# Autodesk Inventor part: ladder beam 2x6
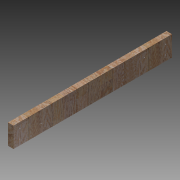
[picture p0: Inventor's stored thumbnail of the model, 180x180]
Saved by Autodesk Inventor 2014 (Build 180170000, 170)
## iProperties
Created: 2013-07
Part Number: ladder beam 2x6
Material: Generic
Document SubType Name: Modeling
Designer: Patrick Rice
Density: 1 g/cm^3
Appearance: Default
Author: Patrick Rice
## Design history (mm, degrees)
sketch "Sketch1"
  geometry: L1 (19.05, -69.85)-(-19.05, -69.85); L2 (-19.05, -69.85)-(-19.05, 69.85); L3 (-19.05, 69.85)-(19.05, 69.85); L4 (19.05, 69.85)-(19.05, -69.85); L5 (19.05, -69.85)-(-19.05, 69.85); L6 (-19.05, -69.85)-(19.05, 69.85); 1 further point
  constraints: 12 end point, 2 midpoint, 2 parallel, 1 horizontal, 1 perpendicular
  dimensions: "d0" = 139.7 distance of L1.end L2.end; "d1" = 38.1 distance of L2.end L3.end
extrude "Extrusion1" new body sketch "Sketch1" distance "d2" = 1092.2; taper "d3" = 0 deg
hole "Hole1" diameter "d6" = 6.35; stored, may be unused: countersink angle "d10" = 82 deg, drill point angle "d12" = 118 deg; dims "d4" = 38.1, "d5" = 44.45, "d7" = 19.05, "d8" = 9.525, "d9" = 6.35, "d11" = 25.4
hole "Hole2" diameter "d15" = 6.35; stored, may be unused: countersink angle "d19" = 82 deg, drill point angle "d21" = 118 deg; dims "d13" = 44.45, "d14" = 38.1, "d16" = 19.05, "d17" = 9.525, "d18" = 6.35, "d20" = 25.4
hole "Hole3" diameter "d24" = 6.35; stored, may be unused: countersink angle "d28" = 82 deg, drill point angle "d30" = 118 deg; dims "d22" = 190.5, "d23" = 44.45, "d25" = 19.05, "d26" = 9.525, "d27" = 6.35, "d29" = 25.4
hole "Hole4" diameter "d33" = 6.35; stored, may be unused: countersink angle "d37" = 82 deg, drill point angle "d39" = 118 deg; dims "d31" = 44.45, "d32" = 190.5, "d34" = 19.05, "d35" = 9.525, "d36" = 6.35, "d38" = 25.4
hole "Hole5" diameter "d42" = 6.35; stored, may be unused: countersink angle "d46" = 82 deg, drill point angle "d48" = 118 deg; dims "d40" = 44.5262, "d41" = 38.1, "d43" = 19.05, "d44" = 9.525, "d45" = 6.35, "d47" = 25.4
hole "Hole6" diameter "d51" = 6.35; stored, may be unused: countersink angle "d55" = 82 deg, drill point angle "d57" = 118 deg; dims "d49" = 38.1, "d50" = 44.45, "d52" = 19.05, "d53" = 9.525, "d54" = 6.35, "d56" = 25.4
body "Solid1"
